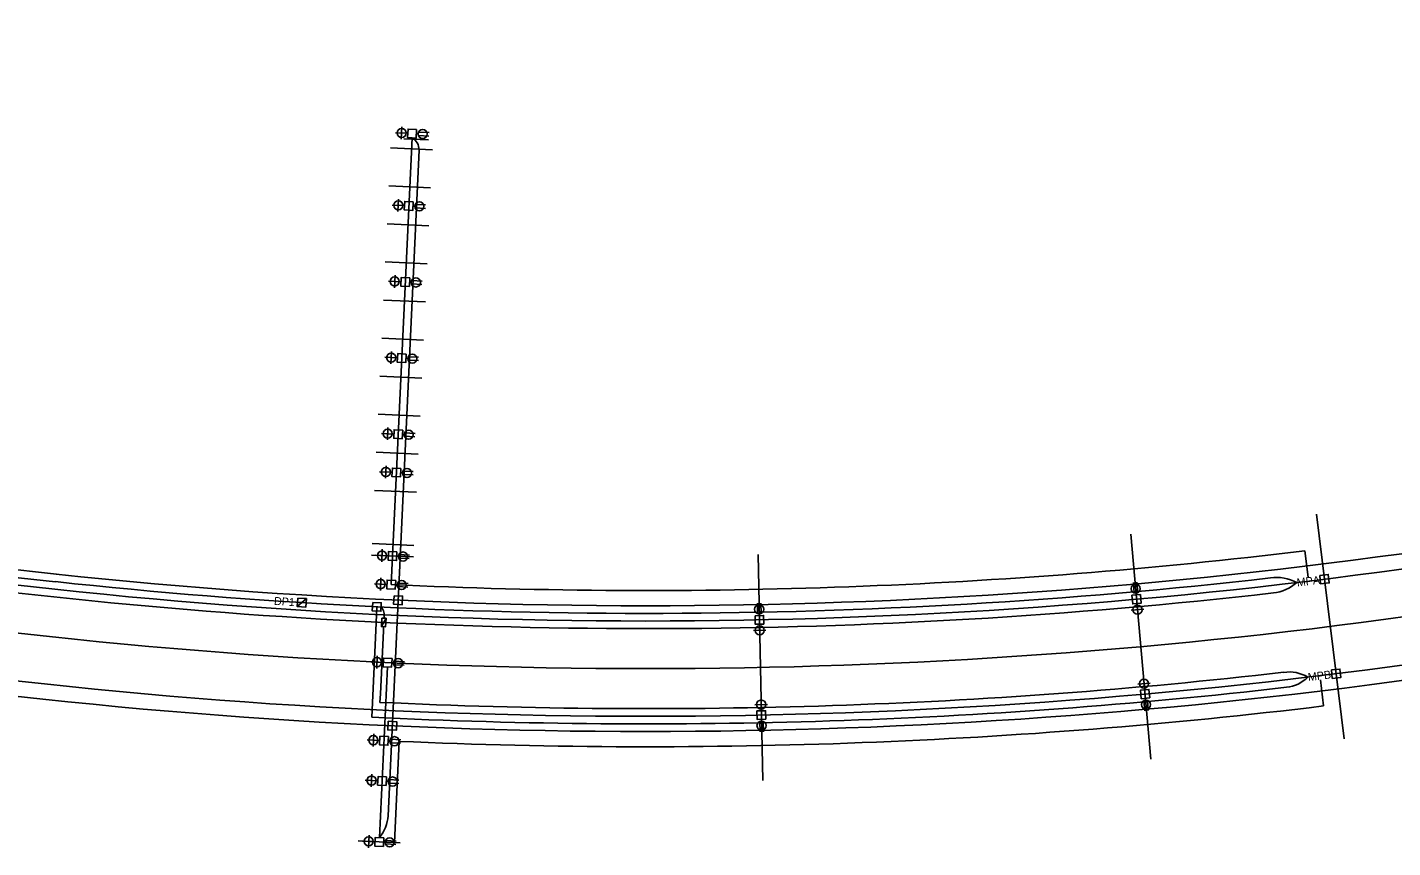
# Model space of a CAD drawing. Extents: x 927572 to 929124, y 636573 to 637910.
# Drawn here: x 927750.6 to 927929.8, y 636573.1 to 636680.7 of the extents above; entities that cross this region are included whole.
import ezdxf

# ---------------------------------------------------------------- set-up
doc = ezdxf.new("R2010")
doc.units = 0
for name, color, linetype in [('ConduitOT', 7, 'Continuous'), ('Miscellaneous4', 7, 'Continuous'), ('Miscellaneous7', 7, 'Continuous'), ('ScratchEle_dp', 7, 'Continuous')]:
    doc.layers.add(name, color=color, linetype=linetype)

msp = doc.modelspace()

# ---------------------------------------------------------------- linework, layer by layer
at = {"layer": 'ConduitOT'}
for p, q in [((927798.39, 636607.59), (927801.12, 636666.21)), ((927797.98, 636577.27), (927802.04, 636664.59)), ((927754.35, 636607.97), (927574.88, 636627.31)), ((927754.46, 636608.97), (927584.84, 636627.24)), ((927754.13, 636605.98), (927574.66, 636625.32)), ((927754.24, 636606.98), (927599.11, 636623.69)), ((927918.68, 636608.57), (927918.26, 636612.01)), ((927752.69, 636592.56), (927582.7, 636610.87)), ((927752.9, 636594.55), (927597.77, 636611.26)), ((927796.36, 636601.56), (927796.5, 636604.67)), ((927795.83, 636590.19), (927796.36, 636601.56)), ((927796.97, 636593.27), (927797.36, 636601.51)), ((927797.36, 636601.51), (927797.38, 636602.07)), ((927797.89, 636596.79), (927796.85, 636574.39)), ((927920.3, 636595.11), (927920.72, 636591.66)), ((927796.92, 636592.14), (927796.97, 636593.27)), ((927798.82, 636573.73), (927799.44, 636587.02)), ((927796.82, 636573.82), (927798.82, 636573.73))]:
    msp.add_line(p, q, dxfattribs=at)
for centre, radius, start, end in [((927831.84, 637327.26), 722.45, 263.8509, 296.49836), ((927831.84, 637327.26), 724.45, 263.8509, 296.49836), ((927831.84, 637327.26), 736.95, 263.8509, 296.49836), ((927831.84, 637327.26), 738.95, 263.8509, 296.49836), ((927800.3, 636664.67), 1.74, 357.3388, 62.1136), ((927831.84, 637327.26), 720.45, 267.33881, 276.88955), ((927831.84, 637327.26), 723.45, 263.8509, 276.5018), ((927914.59, 636603.05), 5.47, 61.4672, 98.7401), ((927913.51, 636612.04), 5.58, 276.5146, 311.4843), ((927831.84, 637327.26), 725.45, 263.8509, 276.51433), ((927795.92, 636603.58), 1.56, 345.5523, 42.9674), ((927831.84, 637327.26), 735.95, 267.28042, 276.52678), ((927916.22, 636591.44), 4.69, 58.5599, 98.952), ((927831.84, 637327.26), 737.95, 267.20293, 276.53817), ((927915.32, 636598.88), 4.8, 276.5385, 314.3294), ((927831.84, 637327.26), 740.95, 267.49346, 276.8895), ((927793.19, 636577.49), 4.79, 319.6597, 357.3388)]:
    msp.add_arc(centre, radius, start, end, dxfattribs=at)
at = {"layer": 'Miscellaneous4'}
for p, q in [((927799.8, 636667.66), (927799.72, 636666.02)), ((927800.58, 636666.8), (927798.94, 636666.88)), ((927801.7, 636666.75), (927801.93, 636666.74)), ((927803.33, 636666.44), (927801.96, 636666.51)), ((927803.36, 636666.89), (927801.98, 636666.96)), ((927800.14, 636657.31), (927798.5, 636657.39)), ((927799.36, 636658.17), (927799.28, 636656.53)), ((927801.26, 636657.26), (927801.49, 636657.25)), ((927802.89, 636656.95), (927801.52, 636657.02)), ((927802.91, 636657.4), (927801.54, 636657.47)), ((927798.89, 636648.18), (927798.81, 636646.54)), ((927799.67, 636647.32), (927798.03, 636647.4)), ((927800.8, 636647.27), (927801.02, 636647.26)), ((927802.43, 636646.96), (927801.06, 636647.03)), ((927802.45, 636647.41), (927801.08, 636647.48)), ((927799.21, 636637.33), (927797.57, 636637.41)), ((927798.43, 636638.19), (927798.35, 636636.55)), ((927800.33, 636637.28), (927800.56, 636637.27)), ((927801.96, 636636.97), (927800.59, 636637.04)), ((927801.99, 636637.42), (927800.61, 636637.49)), ((927797.96, 636628.2), (927797.89, 636626.56)), ((927798.75, 636627.34), (927797.1, 636627.42)), ((927799.87, 636627.29), (927800.09, 636627.28)), ((927801.5, 636626.99), (927800.13, 636627.05)), ((927801.52, 636627.43), (927800.15, 636627.5)), ((927797.73, 636623.18), (927797.65, 636621.54)), ((927798.51, 636622.32), (927796.87, 636622.4)), ((927799.64, 636622.27), (927799.86, 636622.26)), ((927801.27, 636621.97), (927799.89, 636622.03)), ((927801.29, 636622.41), (927799.92, 636622.48)), ((927797.22, 636612.22), (927797.14, 636610.58)), ((927798, 636611.36), (927796.36, 636611.44)), ((927799.13, 636611.31), (927799.35, 636611.3)), ((927800.76, 636611), (927799.38, 636611.07)), ((927800.78, 636611.45), (927799.41, 636611.52)), ((927797.04, 636608.47), (927796.97, 636606.83)), ((927797.83, 636607.61), (927796.19, 636607.68)), ((927798.95, 636607.56), (927799.18, 636607.55)), ((927800.58, 636607.26), (927799.21, 636607.33)), ((927800.6, 636607.71), (927799.23, 636607.77)), ((927895.77, 636607.85), (927895.89, 636606.48)), ((927896.22, 636607.89), (927896.34, 636606.52)), ((927846.43, 636605.16), (927846.46, 636603.79)), ((927846.88, 636605.17), (927846.91, 636603.8)), ((927896.14, 636606.23), (927896.12, 636606.46)), ((927896.24, 636605.11), (927896.38, 636603.48)), ((927846.69, 636603.52), (927846.68, 636603.75)), ((927895.49, 636604.22), (927897.13, 636604.37)), ((927845.91, 636601.56), (927847.55, 636601.6)), ((927846.71, 636602.4), (927846.74, 636600.76)), ((927796.57, 636598.24), (927796.49, 636596.59)), ((927797.35, 636597.37), (927795.71, 636597.45)), ((927798.48, 636597.32), (927798.7, 636597.31)), ((927800.11, 636597.02), (927798.73, 636597.08)), ((927800.13, 636597.47), (927798.76, 636597.53)), ((927897.99, 636594.67), (927896.36, 636594.53)), ((927897.25, 636593.78), (927897.1, 636595.42)), ((927846.94, 636591.03), (927846.91, 636592.67)), ((927897.27, 636591.01), (927897.15, 636592.37)), ((927897.35, 636592.66), (927897.37, 636592.44)), ((927897.72, 636591.05), (927897.6, 636592.41)), ((927847.75, 636591.87), (927846.11, 636591.83)), ((927846.78, 636588.26), (927846.75, 636589.63)), ((927846.97, 636589.9), (927846.97, 636589.68)), ((927847.23, 636588.26), (927847.2, 636589.64)), ((927796.88, 636587.14), (927795.24, 636587.21)), ((927796.1, 636588), (927796.02, 636586.35)), ((927798, 636587.08), (927798.23, 636587.07)), ((927799.65, 636587.23), (927798.28, 636587.29)), ((927799.63, 636586.78), (927798.26, 636586.84)), ((927796.63, 636581.84), (927794.99, 636581.92)), ((927795.85, 636582.7), (927795.77, 636581.06)), ((927797.75, 636581.79), (927797.98, 636581.78)), ((927799.39, 636581.48), (927798.01, 636581.55)), ((927799.41, 636581.93), (927798.03, 636582)), ((927795.48, 636574.71), (927795.4, 636573.07)), ((927796.26, 636573.85), (927794.62, 636573.93)), ((927797.38, 636573.8), (927797.61, 636573.79)), ((927799.01, 636573.49), (927797.64, 636573.56)), ((927799.04, 636573.94), (927797.66, 636574.01))]:
    msp.add_line(p, q, dxfattribs=at)
for centre in [(927799.76, 636666.84), (927802.52, 636666.71), (927799.32, 636657.35), (927802.08, 636657.22), (927798.85, 636647.36), (927801.62, 636647.23), (927798.39, 636637.37), (927801.15, 636637.24), (927797.92, 636627.38), (927800.69, 636627.25), (927797.69, 636622.36), (927800.46, 636622.23), (927797.18, 636611.4), (927799.95, 636611.27), (927797.01, 636607.65), (927799.77, 636607.53), (927896.06, 636607.05), (927846.67, 636604.35), (927896.31, 636604.29), (927846.73, 636601.58), (927796.53, 636597.41), (927799.3, 636597.28), (927897.17, 636594.6), (927846.93, 636591.85), (927897.42, 636591.84), (927846.98, 636589.08), (927796.06, 636587.18), (927798.82, 636587.04), (927795.81, 636581.88), (927798.58, 636581.75), (927795.44, 636573.89), (927798.2, 636573.76)]:
    msp.add_circle(centre, 0.597, dxfattribs=at)
at = {"layer": 'Miscellaneous7'}
for p, q in [((927786.06, 636604.7), (927787.26, 636605.75)), ((927787.26, 636605.75), (927786.06, 636604.7)), ((927797.1, 636602.08), (927797.72, 636603.18))]:
    msp.add_line(p, q, dxfattribs=at)
for points in [[(927801.73, 636667.31), (927801.68, 636666.18), (927800.55, 636666.24), (927800.61, 636667.36)], [(927801.29, 636657.82), (927801.24, 636656.69), (927800.11, 636656.75), (927800.17, 636657.87)], [(927800.82, 636647.83), (927800.77, 636646.71), (927799.65, 636646.76), (927799.7, 636647.88)], [(927800.36, 636637.84), (927800.31, 636636.72), (927799.18, 636636.77), (927799.24, 636637.89)], [(927799.9, 636627.85), (927799.84, 636626.73), (927798.72, 636626.78), (927798.77, 636627.9)], [(927799.66, 636622.83), (927799.61, 636621.71), (927798.49, 636621.76), (927798.54, 636622.88)], [(927799.15, 636611.87), (927799.1, 636610.74), (927797.98, 636610.8), (927798.03, 636611.92)], [(927920.21, 636608.79), (927921.33, 636608.92), (927921.46, 636607.8), (927920.34, 636607.67)], [(927798.98, 636608.12), (927798.93, 636607), (927797.8, 636607.05), (927797.85, 636608.17)], [(927786.13, 636605.82), (927787.26, 636605.75), (927787.18, 636604.62), (927786.06, 636604.7)], [(927795.97, 636605.26), (927797.09, 636605.21), (927797.04, 636604.08), (927795.91, 636604.14)], [(927798.76, 636606.13), (927799.89, 636606.08), (927799.83, 636604.95), (927798.71, 636605.01)], [(927895.58, 636606.18), (927896.7, 636606.28), (927896.8, 636605.16), (927895.68, 636605.06)], [(927797.15, 636603.2), (927797.72, 636603.18), (927797.66, 636602.05), (927797.1, 636602.08)], [(927846.13, 636603.51), (927847.25, 636603.54), (927847.27, 636602.41), (927846.15, 636602.39)], [(927798.5, 636597.88), (927798.45, 636596.76), (927797.33, 636596.81), (927797.38, 636597.94)], [(927921.75, 636596.39), (927922.86, 636596.51), (927922.99, 636595.4), (927921.87, 636595.27)], [(927897.91, 636592.71), (927896.79, 636592.61), (927896.69, 636593.73), (927897.81, 636593.83)], [(927847.53, 636589.91), (927846.4, 636589.89), (927846.38, 636591.02), (927847.51, 636591.04)], [(927798, 636589.65), (927799.12, 636589.6), (927799.07, 636588.47), (927797.94, 636588.53)], [(927798.03, 636587.64), (927797.97, 636586.52), (927796.85, 636586.57), (927796.9, 636587.7)], [(927797.78, 636582.35), (927797.73, 636581.23), (927796.6, 636581.28), (927796.66, 636582.4)], [(927797.41, 636574.36), (927797.36, 636573.23), (927796.23, 636573.29), (927796.29, 636574.41)]]:
    msp.add_lwpolyline(points, close=True, dxfattribs=at)
msp.add_lwpolyline([(927786.06, 636604.7), (927787.18, 636604.62), (927787.26, 636605.75)], dxfattribs=at)
at = {"layer": 'ScratchEle_dp'}
for p, q in [((927803.29, 636665.93), (927800.04, 636666.08)), ((927798.3, 636664.9), (927803.8, 636664.65)), ((927798.07, 636659.91), (927803.56, 636659.65)), ((927797.84, 636654.91), (927803.33, 636654.66)), ((927797.61, 636649.92), (927803.1, 636649.66)), ((927797.37, 636644.92), (927802.87, 636644.67)), ((927797.14, 636639.93), (927802.63, 636639.67)), ((927796.91, 636634.94), (927802.4, 636634.68)), ((927796.68, 636629.94), (927802.17, 636629.69)), ((927796.44, 636624.95), (927801.94, 636624.69)), ((927571.53, 636620.38), (927753.57, 636600.76)), ((927796.21, 636619.95), (927801.71, 636619.7)), ((927923.42, 636587.37), (927919.78, 636616.82)), ((927898.06, 636584.67), (927895.43, 636614.22)), ((927795.89, 636612.96), (927801.38, 636612.7)), ((927795.82, 636611.46), (927801.31, 636611.21)), ((927847.13, 636581.88), (927846.52, 636611.54)), ((927799.57, 636573.7), (927794.07, 636573.95))]:
    msp.add_line(p, q, dxfattribs=at)
msp.add_arc((927831.84, 637327.26), 730.7, 263.8509, 296.49836, dxfattribs=at)

# ---------------------------------------------------------------- texts
at = {"layer": 'Miscellaneous4'}
for s, rotation, p in [('MPA', 6.7613, (927917.27, 636607.34)), ('MPB', 6.8099, (927918.73, 636594.93))]:
    msp.add_text(s, height=1.05, rotation=rotation, dxfattribs=at).set_placement(p)
at = {"layer": 'Miscellaneous7'}
msp.add_text('DP1', height=1.05, rotation=356.2693, dxfattribs=at).set_placement((927782.99, 636604.93))

doc.saveas('drawing.dxf')
